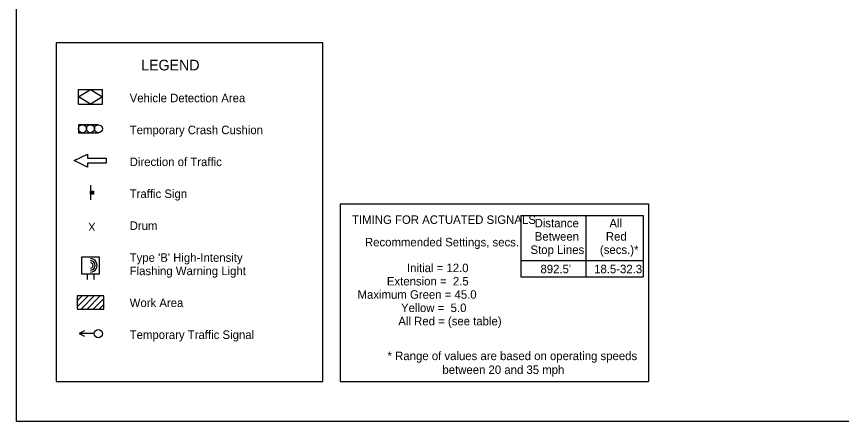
# Model space of a CAD drawing. Extents: x -2134934 to -2119606, y -2139046 to -2137036.
# Drawn here: x -2130232 to -2128679, y -2139046 to -2138285 of the extents above; entities that cross this region are included whole.
import ezdxf

# ---------------------------------------------------------------- set-up
doc = ezdxf.new("R2010")
doc.units = 0
for name, color, linetype in [('Default', 7, 'Continuous'), ('Level 2', 7, 'Continuous'), ('Level 3', 7, 'Continuous'), ('Level 4', 7, 'Continuous')]:
    doc.layers.add(name, color=color, linetype=linetype)

msp = doc.modelspace()

# ---------------------------------------------------------------- linework, layer by layer
at = {"layer": 'Default'}
msp.add_lwpolyline([(-2130232, -2137035.9), (-2127097, -2137035.9), (-2127097, -2139045.9), (-2130232, -2139045.9)], close=True, dxfattribs=at)
at = {"layer": 'Level 2'}
for p, q in [((-2130115.3, -2138449.1), (-2130115.3, -2138422.1)), ((-2130115.3, -2138422.1), (-2130070.3, -2138422.1)), ((-2130070.3, -2138449.1), (-2130070.3, -2138422.1)), ((-2130115.3, -2138449.1), (-2130070.3, -2138449.1)), ((-2130115.3, -2138488.1), (-2130115.3, -2138503.1)), ((-2130077.8, -2138488.1), (-2130115.3, -2138488.1)), ((-2130115.3, -2138503.1), (-2130077.8, -2138503.1)), ((-2130092.8, -2138601.9), (-2130092.8, -2138629.4)), ((-2130092.4, -2138618.4), (-2130092.4, -2138612.8)), ((-2130092.1, -2138612.8), (-2130092.1, -2138618.4)), ((-2130091.9, -2138618.4), (-2130091.9, -2138612.8)), ((-2130091.6, -2138612.8), (-2130091.6, -2138618.4)), ((-2130091.4, -2138618.4), (-2130091.4, -2138612.8)), ((-2130091.2, -2138612.8), (-2130091.2, -2138618.4)), ((-2130090.8, -2138618.4), (-2130090.8, -2138612.8)), ((-2130090.6, -2138612.8), (-2130090.6, -2138618.4)), ((-2130090.3, -2138618.4), (-2130090.4, -2138612.8)), ((-2130090, -2138612.8), (-2130090, -2138618.4)), ((-2130089.6, -2138618.4), (-2130089.6, -2138612.8)), ((-2130089.2, -2138612.8), (-2130089.2, -2138618.4)), ((-2130089, -2138618.4), (-2130089, -2138612.8)), ((-2130088.6, -2138612.8), (-2130088.6, -2138618.4)), ((-2130088.3, -2138618.4), (-2130088.3, -2138612.8)), ((-2130088, -2138612.8), (-2130088, -2138618.4)), ((-2130087.8, -2138618.4), (-2130087.8, -2138612.8)), ((-2130087.5, -2138612.8), (-2130087.5, -2138618.4)), ((-2129622.5, -2138636.9), (-2129622.5, -2138970.9)), ((-2129622.5, -2138636.9), (-2129042.5, -2138636.9)), ((-2129042.5, -2138636.9), (-2129042.5, -2138970.9)), ((-2130099.1, -2138768.8), (-2130099.1, -2138778.8)), ((-2130086.6, -2138768.8), (-2130086.6, -2138778.8)), ((-2130117.8, -2138830.5), (-2130096.8, -2138809.5)), ((-2130117.8, -2138819.2), (-2130108.1, -2138809.5)), ((-2130110.5, -2138834.5), (-2130085.5, -2138809.5)), ((-2130099.2, -2138834.5), (-2130074.2, -2138809.5)), ((-2130087.9, -2138834.5), (-2130067.8, -2138814.5)), ((-2130076.6, -2138834.5), (-2130067.8, -2138825.8)), ((-2130085.7, -2138880.6), (-2130113.6, -2138880.6)), ((-2129622.5, -2138970.9), (-2129042.5, -2138970.9))]:
    msp.add_line(p, q, dxfattribs=at)
for points in [[(-2130157, -2138970.9), (-2129655.4, -2138970.9), (-2129655.4, -2138334.3), (-2130157, -2138334.3)], [(-2130063.1, -2138550.6), (-2130063.1, -2138560.6), (-2130098.1, -2138560.6), (-2130098.1, -2138568.1), (-2130123.1, -2138555.6), (-2130098.1, -2138543.1), (-2130098.1, -2138550.6)], [(-2130092.7, -2138618.4), (-2130092.7, -2138612.7), (-2130087.1, -2138612.7), (-2130087.1, -2138618.4)], [(-2130109.1, -2138768.8), (-2130109.1, -2138736.3), (-2130076.6, -2138736.3), (-2130076.6, -2138768.8)], [(-2130117.8, -2138834.5), (-2130067.8, -2138834.5), (-2130067.8, -2138809.5), (-2130117.8, -2138809.5)]]:
    msp.add_lwpolyline(points, close=True, dxfattribs=at)
msp.add_lwpolyline([(-2130104, -2138875.7), (-2130114, -2138880.7), (-2130104, -2138885.7)], dxfattribs=at)
for centre, radius in [((-2130107.8, -2138495.6), 7.5), ((-2130107.8, -2138495.6), 7.5), ((-2130092.8, -2138495.6), 7.5), ((-2130092.8, -2138495.6), 7.5), ((-2130077.8, -2138495.6), 7.5), ((-2130077.8, -2138495.6), 7.5), ((-2130077.9, -2138880.9), 7.74)]:
    msp.add_circle(centre, radius, dxfattribs=at)
for radius in [12.5, 12.5, 8.75, 5]:
    msp.add_arc((-2130092.8, -2138752.5), radius, 269.4041, 90.5445, dxfattribs=at)
at = {"layer": 'Level 3'}
for p, q in [((-2129282.5, -2138658.5), (-2129282.5, -2138774)), ((-2129282.5, -2138658.5), (-2129052.5, -2138658.5)), ((-2129160.2, -2138658.5), (-2129160.2, -2138774)), ((-2129052.5, -2138658.5), (-2129052.5, -2138774)), ((-2129282.5, -2138743.5), (-2129052.5, -2138743.5)), ((-2129282.5, -2138774), (-2129052.5, -2138774))]:
    msp.add_line(p, q, dxfattribs=at)
at = {"layer": 'Level 4'}
msp.add_lwpolyline([(-2130115.3, -2138435.6), (-2130092.8, -2138422.1), (-2130070.3, -2138435.6), (-2130092.8, -2138449.1)], close=True, dxfattribs=at)

# ---------------------------------------------------------------- texts
at = {"layer": 'Level 2'}
msp.add_text('X', height=15, rotation=180, dxfattribs=at).set_placement((-2130083.4, -2138672.2))
at = {"layer": 'Level 3'}
for s, height, p in [('LEGEND', 20, (-2129997.3, -2138385.9)), ('Vehicle Detection Area', 16, (-2130018.9, -2138445.8)), ('Temporary Crash Cushion', 16, (-2130018.9, -2138505.8)), ('Direction of Traffic', 16, (-2130018.9, -2138565.8)), ('Traffic Sign', 16, (-2130018.9, -2138625.8)), ('Drum', 16, (-2130018.9, -2138685.8)), ('TIMING FOR ACTUATED SIGNALS', 16, (-2129600.2, -2138674.5)), ('Distance', 16, (-2129256.6, -2138681)), ('All', 16, (-2129115.8, -2138681)), ('Recommended Settings, secs.', 16, (-2129576, -2138716.8)), ('Between', 16, (-2129256.3, -2138706)), ('Red', 16, (-2129122.5, -2138706)), ('Stop Lines', 16, (-2129264.3, -2138731)), (' (secs.)*', 16, (-2129139.6, -2138731)), ("Type 'B' High-Intensity", 16, (-2130018.9, -2138745.8)), ('Initial = 12.0', 16, (-2129496.9, -2138765.2)), ('Flashing Warning Light', 16, (-2130018.9, -2138770.8)), ("892.5'", 16, (-2129245.6, -2138767.3)), ('18.5-32.3', 16, (-2129144.6, -2138767.3)), ('Extension =  2.5', 16, (-2129534.7, -2138790.2)), ('Maximum Green = 45.0', 16, (-2129589.9, -2138815.2)), ('Work Area', 16, (-2130018.9, -2138830.8)), ('Yellow =  5.0', 16, (-2129508.1, -2138840.2)), ('All Red = (see table)', 16, (-2129513.2, -2138865.2)), ('Temporary Traffic Signal', 16, (-2130018.9, -2138890.8)), ('* Range of values are based on operating speeds', 16, (-2129533.4, -2138930.6)), ('between 20 and 35 mph', 16, (-2129430.2, -2138956.6))]:
    msp.add_text(s, height=height, dxfattribs=at).set_placement(p)

doc.saveas('drawing.dxf')
